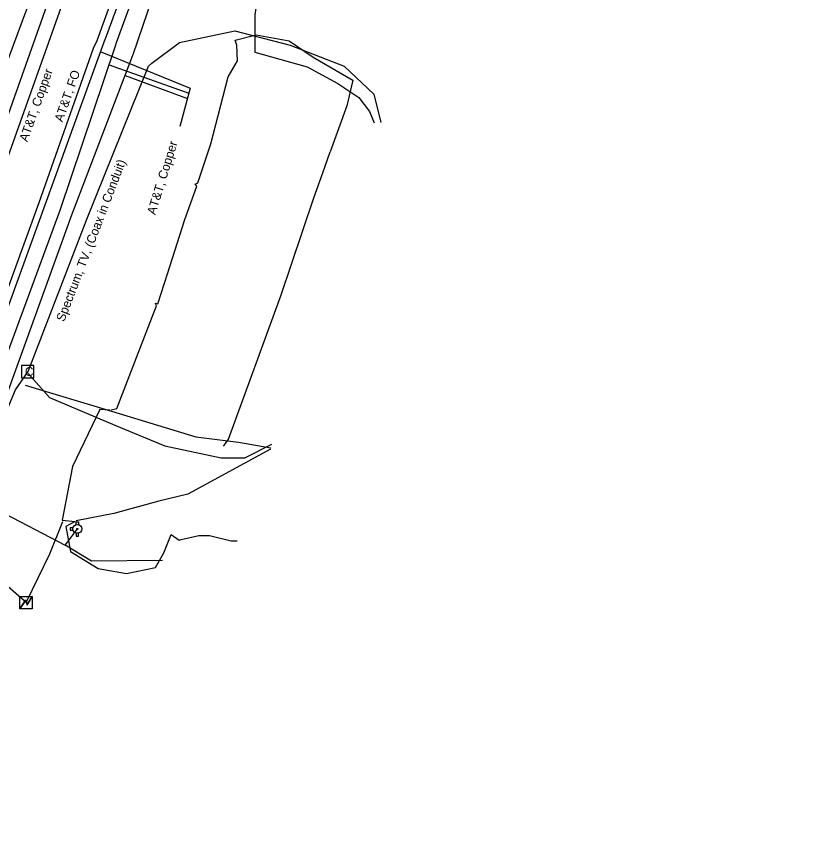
# Model space of a CAD drawing. Extents: x 2070721 to 2083340, y 729290 to 737883.
# Drawn here: x 2081212.7 to 2081564.9, y 733203.8 to 733578.3 of the extents above; entities that cross this region are included whole.
import ezdxf

# ---------------------------------------------------------------- set-up
doc = ezdxf.new("R2010")
doc.units = 0
for name, color, linetype in [('Exist Utilities Gas UG Line SUE LOS B', 7, 'Continuous'), ('Exist Utilities Power Transformer CELL', 7, 'Continuous'), ('Exist Utilities Power UG Cable SUE LOS B', 7, 'Continuous'), ('Exist Utilities Telephone UG Cable SUE LOS C', 7, 'Continuous'), ('Exist Utilities Telephone UG Cable SUE LOS C Leader', 7, 'Continuous'), ('Exist Utilities Telephone UG Cable SUE LOS C Text', 7, 'Continuous'), ('Exist Utilities Telephone UG FO SUE LOS B', 7, 'Continuous'), ('Exist Utilities Telephone UG FO SUE LOS B Text', 7, 'Continuous'), ('Exist Utilities TV Pedestal CELL', 7, 'Continuous'), ('Exist Utilities TV UG Cable SUE LOS B', 7, 'Continuous'), ('Exist Utilities TV UG Cable SUE LOS B Text', 7, 'Continuous'), ('Exist Utilities Water Fire Hydrant CELL', 7, 'Continuous'), ('Exist Utilities Water UG Line SUE LOS B', 7, 'Continuous')]:
    doc.layers.add(name, color=color, linetype=linetype)

msp = doc.modelspace()

# ---------------------------------------------------------------- linework, layer by layer
at = {"layer": 'Exist Utilities Gas UG Line SUE LOS B'}
msp.add_lwpolyline([(2081157.6, 733423.49), (2081157.75, 733423.93), (2081190.43, 733509.93), (2081219.7, 733588.19), (2081252.91, 733674.58), (2081286.02, 733770.88), (2081302.57, 733820.59), (2081312.47, 733846.89)], dxfattribs=at)
at = {"layer": 'Exist Utilities Power Transformer CELL'}
msp.add_line((2081216.97, 733315.56), (2081216.97, 733315.56), dxfattribs=at)
msp.add_lwpolyline([(2081214.13, 733318.17), (2081219.68, 733318.17), (2081219.68, 733312.62), (2081214.13, 733312.62)], close=True, dxfattribs=at)
for points in [[(2081214.13, 733312.62), (2081216.77, 733316.56), (2081217.4, 733314.35), (2081219.68, 733318.17)], [(2081214.2, 733312.62), (2081216.77, 733316.35), (2081217.36, 733314.17), (2081219.68, 733318.02)]]:
    msp.add_lwpolyline(points, dxfattribs=at)
at = {"layer": 'Exist Utilities Power UG Cable SUE LOS B'}
for points in [[(2081255.08, 733401.83), (2081257.7, 733402.5), (2081266.54, 733425.38), (2081275.48, 733448.49), (2081274.96, 733449.76), (2081276.11, 733449.4), (2081280.42, 733462.89), (2081288.23, 733487.19), (2081293.53, 733502.2), (2081292.78, 733503.17), (2081293.98, 733503.64), (2081299.88, 733521.18), (2081307.63, 733551.29), (2081311.78, 733558.44), (2081311.53, 733565.53), (2081310.75, 733567.69), (2081320.22, 733570.19), (2081335.06, 733567.36), (2081345.85, 733560.11), (2081363.58, 733549.71), (2081360.92, 733538.3), (2081353.48, 733517.62)], [(2081305.65, 733385.58), (2081305.68, 733385.74), (2081307.72, 733388.7), (2081331.3, 733452.95), (2081346.05, 733496.93), (2081350.09, 733508.16), (2081353.48, 733517.62)], [(2081216.46, 733412.89), (2081255.27, 733401.21), (2081293.04, 733389.74), (2081312.23, 733387.32), (2081326.7, 733384.87)], [(2081254.52, 733401.71), (2081249.97, 733402.02), (2081237.71, 733376.5), (2081233.12, 733352.36), (2081238.98, 733351.69), (2081234.79, 733349.44), (2081236.79, 733338.35), (2081249.32, 733330.71), (2081262.01, 733328.39), (2081275.02, 733331.05), (2081278.71, 733337.68), (2081282.09, 733345.97), (2081285.66, 733343.35), (2081286.57, 733343.74), (2081294.52, 733345.49), (2081299.28, 733345.49), (2081308.93, 733343.11), (2081311.71, 733343.11)], [(2081326.62, 733384.18), (2081289.46, 733364.01), (2081276.44, 733360.9), (2081256.28, 733355.4), (2081239.4, 733352.05)], [(2081122.35, 733359.34), (2081139.09, 733352.49), (2081184.49, 733336.32), (2081197.51, 733330.86), (2081206.4, 733324.71), (2081216.97, 733315.56)], [(2081233.19, 733351.65), (2081227.37, 733337.09), (2081216.98, 733315.54)]]:
    msp.add_lwpolyline(points, dxfattribs=at)
at = {"layer": 'Exist Utilities Telephone UG Cable SUE LOS C'}
for points in [[(2080953.21, 732796.69), (2081054.09, 733077.62), (2081111.09, 733245.57), (2081176.08, 733423.78), (2081231.97, 733580.28), (2081320.16, 733847.08), (2081418.84, 734093.09), (2081467.34, 734224.03), (2081494.06, 734287.2), (2081526.74, 734352.01), (2081556, 734404.62), (2081808.13, 734757.73), (2081845.73, 734804.26), (2081874.67, 734821.58), (2081898.66, 734810.94), (2081917.15, 734795.51)], [(2081252.65, 733568.73), (2081284.23, 733654.98), (2081290.61, 733658.83), (2081296.02, 733657.99)], [(2081257.51, 733566.68), (2081286.37, 733645.5), (2081296.64, 733655.96)], [(2081264.77, 733561.01), (2081264.9, 733561.27), (2081278.02, 733599.54), (2081293.06, 733647.81), (2081297.01, 733655.83)], [(2081324.91, 733613.72), (2081319.52, 733579.11), (2081319.52, 733562.34), (2081343.1, 733555.71), (2081356.84, 733548.33), (2081366.23, 733541.95), (2081371.13, 733535.72), (2081373.21, 733530.68)], [(2080971.45, 732791.05), (2081028.93, 732955.93), (2081037.58, 732965.12), (2081059.34, 733032.5), (2081099.5, 733145.5), (2081127.24, 733222.27), (2081165.53, 733329.08), (2081197.08, 733415.76), (2081225.51, 733493.81), (2081252.34, 733568.18), (2081252.65, 733568.73)], [(2080977.85, 732787.5), (2081009.55, 732879.6), (2081045.87, 732978.13), (2081063.56, 733030.35), (2081103.18, 733143.81), (2081131.57, 733220.23), (2081172.06, 733327.38), (2081203.1, 733413.05), (2081232.13, 733491.49), (2081257.07, 733565.11), (2081257.51, 733566.68)], [(2080980.31, 732787.04), (2081017.13, 732880.26), (2081044.65, 732962.53), (2081058.02, 732999.54), (2081069.26, 733036.84), (2081073.31, 733048.09), (2081079.75, 733057.99), (2081085.51, 733069.49), (2081110.84, 733140.06), (2081139.9, 733217.95), (2081177.19, 733322.59), (2081208.97, 733410.75), (2081237.5, 733489.4), (2081264.77, 733561.01)]]:
    msp.add_lwpolyline(points, dxfattribs=at)
at = {"layer": 'Exist Utilities Telephone UG Cable SUE LOS C Leader'}
for p, q in [((2081254.27, 733556.72), (2081289.92, 733543.99)), ((2081261.33, 733551.91), (2081289.31, 733541.49))]:
    msp.add_line(p, q, dxfattribs=at)
msp.add_lwpolyline([(2081250.19, 733562.64), (2081290.57, 733546.24), (2081285.89, 733528.96)], dxfattribs=at)
at = {"layer": 'Exist Utilities Telephone UG FO SUE LOS B'}
for points in [[(2081248.81, 733567.64), (2081281.2, 733657.22), (2081333.49, 733797.21), (2081369.06, 733900.16), (2081403.11, 733993), (2081427.18, 734053.08), (2081460.75, 734136.42), (2081485.85, 734201.8), (2081501.51, 734239.63), (2081538.45, 734313.8), (2081542.88, 734322.62)], [(2080974.54, 732788.58), (2081004.48, 732877.32), (2081038.77, 732975.1), (2081057.5, 733033.86), (2081097.09, 733146.25), (2081124.3, 733222.73), (2081163.35, 733330.31), (2081194.31, 733416.96), (2081222.79, 733494.92), (2081247.13, 733564.12), (2081248.81, 733567.64)]]:
    msp.add_lwpolyline(points, dxfattribs=at)
at = {"layer": 'Exist Utilities TV Pedestal CELL'}
msp.add_line((2081217.67, 733419.02), (2081217.67, 733419.02), dxfattribs=at)
msp.add_lwpolyline([(2081214.9, 733416.24), (2081220.45, 733416.24), (2081220.45, 733421.79), (2081214.9, 733421.79), (2081214.9, 733416.24)], dxfattribs=at)
at = {"layer": 'Exist Utilities TV UG Cable SUE LOS B'}
for points in [[(2081271.85, 733556.1), (2081273.4, 733557.42), (2081285.71, 733566.63), (2081310.55, 733571.95), (2081335.49, 733565.44), (2081359.75, 733556.12), (2081373.01, 733543.42), (2081376.11, 733530.71)], [(2081121.25, 733358.53), (2081135.11, 733344.16), (2081174.32, 733329.18), (2081179.16, 733332.24), (2081212.15, 733410.86), (2081217.78, 733418.98), (2081244.16, 733487.45), (2081271.85, 733556.1)], [(2081217.8, 733418.14), (2081227.38, 733407.32), (2081256.72, 733394.96), (2081279.22, 733385.68), (2081304.54, 733380.27), (2081315.06, 733380.27), (2081327.24, 733386.44)]]:
    msp.add_lwpolyline(points, dxfattribs=at)
at = {"layer": 'Exist Utilities Water Fire Hydrant CELL'}
msp.add_line((2081239.93, 733348.42), (2081239.93, 733348.42), dxfattribs=at)
for points in [[(2081239.41, 733350.33), (2081239.41, 733351.62), (2081240.44, 733351.62), (2081240.44, 733350.31)], [(2081238.01, 733348.93), (2081236.73, 733348.93), (2081236.73, 733347.91), (2081238.01, 733347.91)], [(2081239.41, 733346.51), (2081239.41, 733345.22), (2081240.44, 733345.22), (2081240.44, 733346.53)]]:
    msp.add_lwpolyline(points, dxfattribs=at)
for radius in [1.98, 0.243]:
    msp.add_circle((2081239.93, 733348.42), radius, dxfattribs=at)
at = {"layer": 'Exist Utilities Water UG Line SUE LOS B'}
msp.add_line((2081202.55, 733357.67), (2081234.51, 733341.1), dxfattribs=at)
for points in [[(2081199.8, 733508.96), (2081200.26, 733510.4), (2081231.43, 733598.04), (2081246.63, 733639.55)], [(2081234.51, 733341.1), (2081235.06, 733341.83), (2081240, 733348.4)], [(2081278.15, 733334.18), (2081246.21, 733333.89), (2081234.51, 733341.1)]]:
    msp.add_lwpolyline(points, dxfattribs=at)

# ---------------------------------------------------------------- texts
at = {"layer": 'Exist Utilities Telephone UG Cable SUE LOS C Text'}
for rotation, p in [(70.3476, (2081217.47, 733521.84)), (72.9166, (2081274.9, 733489.07))]:
    msp.add_text('AT&T, Copper', height=4, rotation=rotation, dxfattribs=at).set_placement(p)
at = {"layer": 'Exist Utilities Telephone UG FO SUE LOS B Text'}
msp.add_text('AT&T, FO', height=4, rotation=70.6203, dxfattribs=at).set_placement((2081233.26, 733530.7))
at = {"layer": 'Exist Utilities TV Pedestal CELL'}
msp.add_text('C', height=4, dxfattribs=at).set_placement((2081216.37, 733417.02))
at = {"layer": 'Exist Utilities TV UG Cable SUE LOS B Text'}
msp.add_text('Spectrum, TV, (Coax in Conduit) ', height=4, rotation=68.9276, dxfattribs=at).set_placement((2081233.99, 733441.12))

doc.saveas('drawing.dxf')
